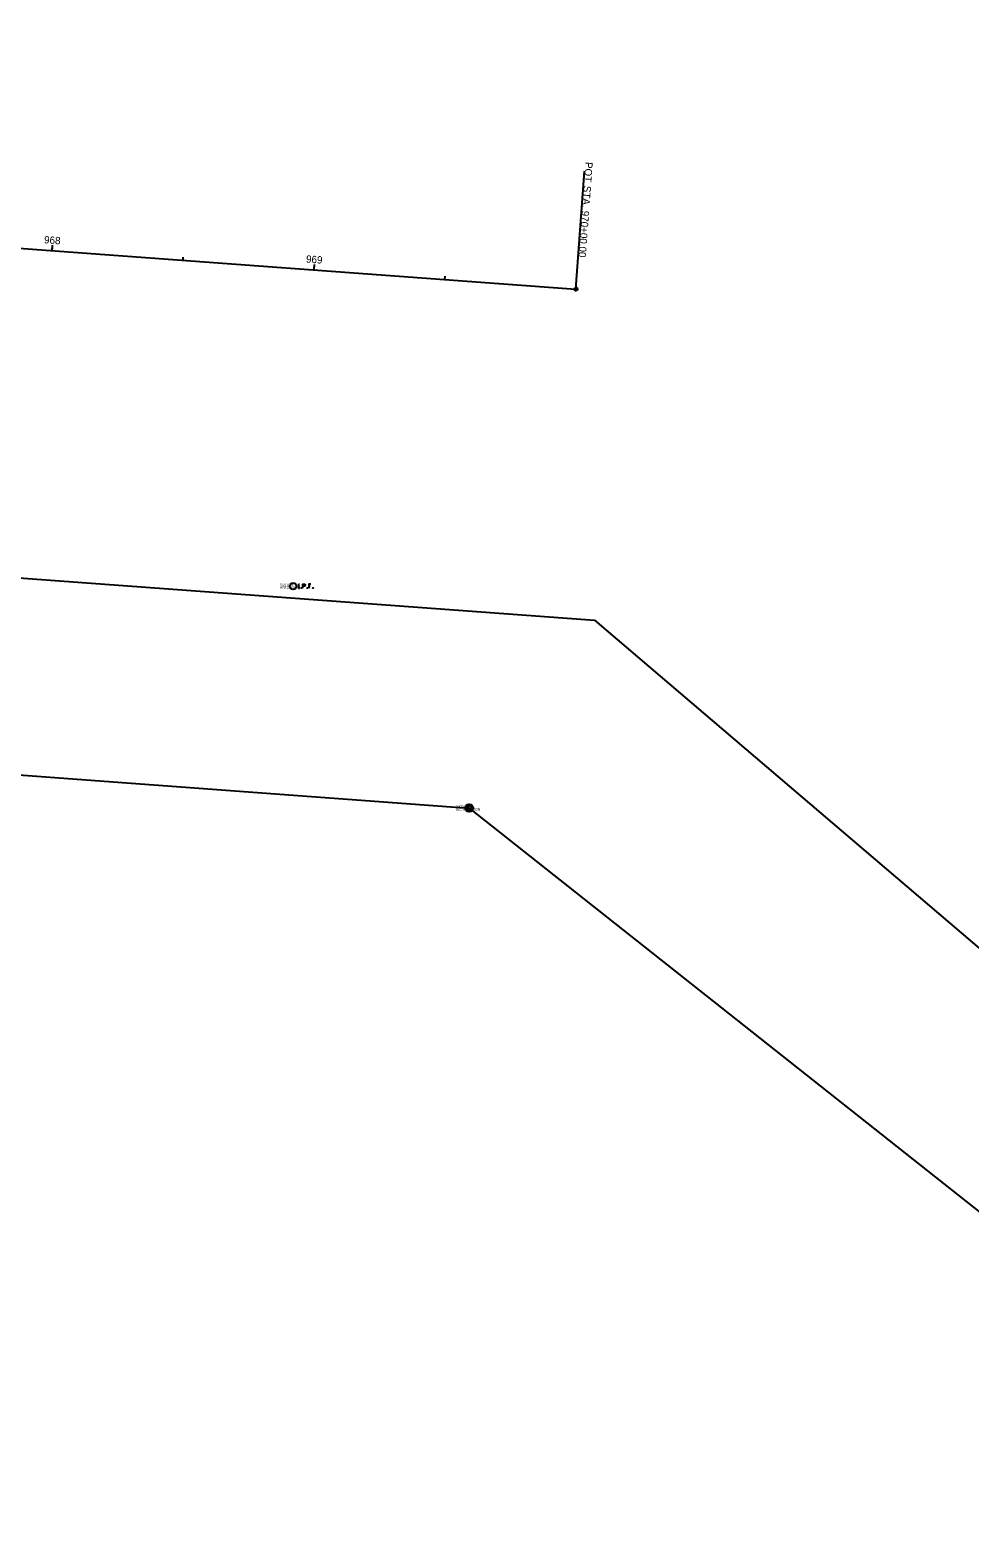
# Model space of a CAD drawing. Extents: x 1981066 to 1984208, y 708139 to 709503.
# Drawn here: x 1983492 to 1983850, y 708395 to 708969 of the extents above; entities that cross this region are included whole.
import ezdxf

# ---------------------------------------------------------------- set-up
doc = ezdxf.new("R2010")
doc.units = 0
for name, color, linetype in [('DR_X_Ditch', 7, 'Continuous'), ('DR_X_Elev_Flow', 7, 'Continuous'), ('LT_X_Poles', 7, 'Continuous'), ('PM_X_Edge_Line', 7, 'Continuous'), ('PV_X_EOP', 7, 'Continuous'), ('RD_X_Wall', 7, 'Continuous'), ('SV_P_Mon_Cells_Set', 7, 'Continuous'), ('SV_X_Break_Lines', 7, 'Continuous'), ('SV_X_Shot_Marker', 7, 'Continuous'), ('SV_X_Toe_of_Slope', 7, 'Continuous'), ('TopoDOT Temp', 7, 'Continuous'), ('UT_X_Misc_Cells', 7, 'Continuous')]:
    doc.layers.add(name, color=color, linetype=linetype)

msp = doc.modelspace()

# ---------------------------------------------------------------- linework, layer by layer
at = {"layer": 'DR_X_Ditch'}
for p, q in [((1982499.31, 708833.12), (1983707.34, 708743.91)), ((1983707.34, 708743.91), (1984112.67, 708398.18))]:
    msp.add_line(p, q, dxfattribs=at)
at = {"layer": 'PM_X_Edge_Line'}
for p, q in [((1983500.79, 708884.67), (1983500.93, 708886.67)), ((1983550.65, 708881), (1983550.74, 708882.2)), ((1983600.52, 708877.33), (1983600.66, 708879.33)), ((1983650.38, 708873.66), (1983650.47, 708874.86))]:
    msp.add_line(p, q, dxfattribs=at)
at = {"layer": 'PV_X_EOP'}
msp.add_line((1983700.25, 708869.99), (1983703.55, 708914.87), dxfattribs=at)
msp.add_circle((1983700.25, 708869.99), 0.6, dxfattribs=at)
at = {"layer": 'RD_X_Wall'}
for p, q in [((1983500.79, 708884.67), (1983500.87, 708885.87)), ((1983600.52, 708877.33), (1983600.6, 708878.53))]:
    msp.add_line(p, q, dxfattribs=at)
at = {"layer": 'SV_P_Mon_Cells_Set'}
msp.add_line((1983700.25, 708869.99), (1983703.55, 708914.87), dxfattribs=at)
msp.add_circle((1983700.25, 708869.99), 0.6, dxfattribs=at)
at = {"layer": 'SV_X_Break_Lines'}
msp.add_line((1982360.68, 708968.58), (1983700.25, 708869.99), dxfattribs=at)
at = {"layer": 'SV_X_Shot_Marker'}
for points in [[(1983594.56, 708757.68), (1983594.92, 708757.68)], [(1983594.56, 708756.08), (1983594.92, 708756.08)], [(1983594.74, 708756.08), (1983594.74, 708757.68)], [(1983595.7, 708756.29), (1983595.75, 708756.29), (1983595.79, 708756.27), (1983595.82, 708756.22), (1983595.82, 708756.15), (1983595.79, 708756.1), (1983595.75, 708756.08), (1983595.7, 708756.08), (1983595.67, 708756.1), (1983595.63, 708756.15), (1983595.63, 708756.22), (1983595.67, 708756.27), (1983595.7, 708756.29)], [(1983596.31, 708756.08), (1983596.31, 708757.68), (1983596.84, 708757.68), (1983596.89, 708757.67), (1983596.97, 708757.64), (1983597, 708757.61), (1983597.03, 708757.59), (1983597.08, 708757.53), (1983597.11, 708757.46), (1983597.13, 708757.36), (1983597.13, 708757.21), (1983597.12, 708757.16), (1983597.1, 708757.09), (1983597.06, 708757), (1983597.01, 708756.96), (1983596.98, 708756.93), (1983596.92, 708756.91), (1983596.84, 708756.9), (1983596.31, 708756.9)], [(1983597.95, 708756.29), (1983598, 708756.29), (1983598.04, 708756.27), (1983598.07, 708756.22), (1983598.07, 708756.15), (1983598.04, 708756.1), (1983598, 708756.08), (1983597.95, 708756.08), (1983597.92, 708756.1), (1983597.88, 708756.15), (1983597.88, 708756.22), (1983597.92, 708756.27), (1983597.95, 708756.29)], [(1983599.32, 708757.68), (1983598.55, 708757.68), (1983598.55, 708756.08)], [(1983598.55, 708756.9), (1983599.09, 708756.9)], [(1983600.1, 708756.29), (1983600.15, 708756.29), (1983600.19, 708756.27), (1983600.22, 708756.22), (1983600.22, 708756.15), (1983600.19, 708756.1), (1983600.15, 708756.08), (1983600.1, 708756.08), (1983600.06, 708756.1), (1983600.03, 708756.15), (1983600.03, 708756.22), (1983600.06, 708756.27), (1983600.1, 708756.29)]]:
    msp.add_lwpolyline(points, dxfattribs=at)
for centre, radius in [((1983592.55, 708756.88), 1.2), ((1983659.59, 708672.43), 1.5), ((1983659.59, 708672.43), 0.8)]:
    msp.add_circle(centre, radius, dxfattribs=at)
at = {"layer": 'SV_X_Toe_of_Slope'}
for p, q in [((1982638.45, 708747.66), (1983659.59, 708672.43)), ((1983659.59, 708672.43), (1984010.5, 708394.56))]:
    msp.add_line(p, q, dxfattribs=at)
at = {"layer": 'TopoDOT Temp'}
msp.add_line((1983700.25, 708869.99), (1983703.55, 708914.87), dxfattribs=at)
msp.add_circle((1983700.25, 708869.99), 0.6, dxfattribs=at)

# ---------------------------------------------------------------- texts
at = {"layer": 'DR_X_Elev_Flow'}
for s, p in [('920.387', (1983587.45, 708755.88)), ('921.652', (1983654.53, 708671.43))]:
    msp.add_text(s, height=1, dxfattribs=at).set_placement(p)
at = {"layer": 'LT_X_Poles'}
for s, p in [('IPIN', (1983592.55, 708755.88)), ('CMON', (1983659.59, 708671.43))]:
    msp.add_text(s, height=1, dxfattribs=at).set_placement(p)
at = {"layer": 'PM_X_Edge_Line'}
for s, p in [('968', (1983497.65, 708887.45)), ('969', (1983597.39, 708880.11))]:
    msp.add_text(s, height=2.8, rotation=355.79057, dxfattribs=at).set_placement(p)
at = {"layer": 'PV_X_EOP'}
for s, p in [('POT', (1983703.86, 708918.48)), (' STA. ', (1983703.27, 708910.46)), ('970+00.00', (1983702.5, 708899.91))]:
    msp.add_text(s, height=2.8, rotation=265.79057, dxfattribs=at).set_placement(p)
at = {"layer": 'SV_P_Mon_Cells_Set'}
for s, p in [('POT', (1983703.86, 708918.48)), (' STA. ', (1983703.27, 708910.46)), ('970+00.00', (1983702.5, 708899.91))]:
    msp.add_text(s, height=2.8, rotation=265.79057, dxfattribs=at).set_placement(p)
at = {"layer": 'TopoDOT Temp'}
for s, p in [('POT', (1983703.86, 708918.48)), (' STA. ', (1983703.27, 708910.46)), ('970+00.00', (1983702.5, 708899.91))]:
    msp.add_text(s, height=2.8, rotation=265.79057, dxfattribs=at).set_placement(p)
at = {"layer": 'UT_X_Misc_Cells'}
for s, p in [('SV1075', (1983587.56, 708756.88)), ('MON60', (1983654.76, 708672.43))]:
    msp.add_text(s, height=1, dxfattribs=at).set_placement(p)

doc.saveas('drawing.dxf')
